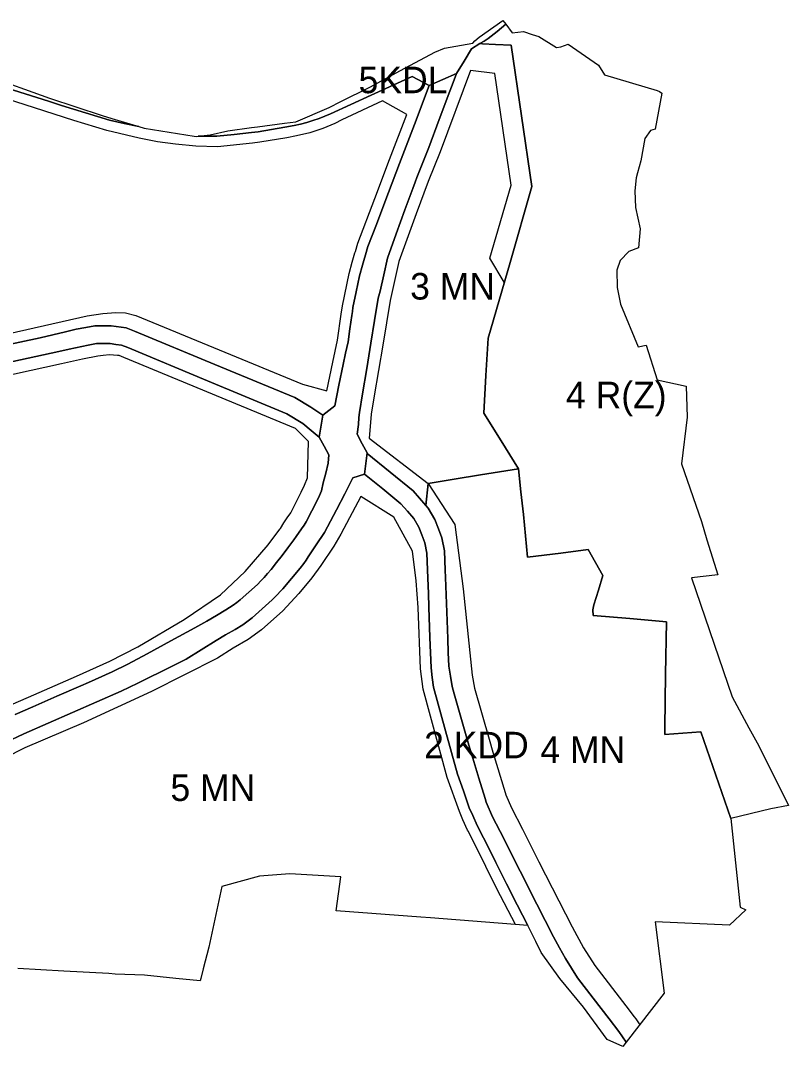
# Model space of a CAD drawing. Extents: x -295551 to -293631, y 22633 to 24461.
# Drawn here: x -294065 to -293631, y 22962 to 23541 of the extents above; entities that cross this region are included whole.
import ezdxf

# ---------------------------------------------------------------- set-up
doc = ezdxf.new("R2010")
doc.units = 0
for name, color, linetype in [('linie_rozgraniczajace', 7, 'Continuous'), ('linie_zabudowy_nieprzekraczalne', 7, 'Continuous'), ('oznaczenia_przeznaczen', 7, 'Continuous')]:
    doc.layers.add(name, color=color, linetype=linetype)

msp = doc.modelspace()

# ---------------------------------------------------------------- linework, layer by layer
at = {"layer": 'linie_rozgraniczajace'}
for points in [[(-293964.167, 23475.628), (-293957.33, 23476.38), (-293947.47, 23478.76), (-293934.05, 23480.5), (-293930.72, 23480.93), (-293915.47, 23482.97), (-293908.99, 23483.73), (-293890.08, 23491.92), (-293883.58, 23495.15), (-293867.11, 23503.35), (-293849.86, 23512.82), (-293830.42, 23523.02), (-293825.1, 23525.31), (-293809.05, 23528.15), (-293807.87, 23529.46), (-293805.42, 23531.6), (-293797.24, 23537.38), (-293792.01, 23540.98), (-293790.43, 23538.838), (-293795.371, 23534.866), (-293800.311, 23530.894), (-293802.683, 23529.408), (-293805.058, 23527.919), (-293809.809, 23524.941), (-293814.01, 23518.017), (-293818.212, 23511.093), (-293825.939, 23507.684), (-293833.667, 23504.275), (-293843.344, 23509.288), (-293866.407, 23498.811), (-293889.47, 23488.334), (-293892.68, 23486.996), (-293895.89, 23485.657), (-293899.332, 23484.511), (-293902.774, 23483.364), (-293906.346, 23482.529), (-293909.918, 23481.695), (-293915.119, 23480.653), (-293922.651, 23479.411), (-293930.183, 23478.169), (-293934.105, 23477.664), (-293943.86, 23476.644), (-293953.614, 23475.624), (-293958.89, 23475.626)], [(-293805.058, 23527.919), (-293802.683, 23529.408), (-293800.311, 23530.894), (-293795.371, 23534.866), (-293790.43, 23538.838), (-293786.87, 23534.01), (-293780.32, 23534.72), (-293775.58, 23533.17), (-293771.7, 23531.9), (-293761.82, 23525.66), (-293759.37, 23526.09), (-293755.26, 23527.56), (-293738.14, 23515.75), (-293734.64, 23510.25), (-293704.88, 23501.49), (-293703.59, 23500.81), (-293702.22, 23500), (-293706.11, 23479.61), (-293708.6, 23478.94), (-293711.95, 23474.38), (-293714.08, 23461.66), (-293716.09, 23454.95), (-293716.77, 23452.14), (-293717.48, 23444.85), (-293717.2, 23435.44), (-293714.56, 23423.34), (-293715.47, 23412.5), (-293720.92, 23410.51), (-293725.77, 23405.35), (-293727.71, 23399.89), (-293727.56, 23390.17), (-293725.63, 23380.77), (-293715.73, 23356.65), (-293711.19, 23357.65), (-293704.98, 23338.1), (-293688.52, 23334.54), (-293687.99, 23316.93), (-293691.21, 23290.55), (-293679.86, 23258.01), (-293676.87, 23247.72), (-293670.56, 23227.96), (-293685.48, 23226.2), (-293662.58, 23159.04), (-293653.07, 23141.45), (-293647.57, 23131.26), (-293630.74, 23097.6), (-293640.78, 23095.7), (-293663.22, 23090.34), (-293671.727, 23114.831), (-293680.234, 23139.321), (-293690.382, 23138.526), (-293700.53, 23137.73), (-293700.59, 23139.73), (-293700.65, 23141.73), (-293700.115, 23171.584), (-293699.581, 23201.438), (-293720.301, 23203.149), (-293741.022, 23204.86), (-293741.29, 23208.12), (-293740.6, 23210.92), (-293738.137, 23219.218), (-293735.674, 23227.516), (-293739.815, 23234.859), (-293743.957, 23242.201), (-293759.393, 23240.121), (-293778.11, 23237.86), (-293779.27, 23249.885), (-293780.43, 23261.91), (-293781.825, 23274.825), (-293783.22, 23287.74), (-293793.026, 23303.498), (-293802.831, 23319.256), (-293801.636, 23340.408), (-293800.44, 23361.56), (-293788.033, 23404.353), (-293775.627, 23447.146), (-293781.519, 23487.114), (-293787.411, 23527.082), (-293796.209, 23527.516), (-293803.567, 23527.879)], [(-293874.295, 23307.377), (-293873.681, 23312.842), (-293873.486, 23316.77), (-293873.101, 23319.613), (-293871.36, 23330.15), (-293868.99, 23344.48), (-293866.62, 23358.81), (-293864.525, 23371.5), (-293862.43, 23384.19), (-293861.42, 23388.08), (-293859.34, 23397.43), (-293857.26, 23406.78), (-293852.37, 23420.455), (-293847.48, 23434.13), (-293845.22, 23440.161), (-293842.961, 23446.192), (-293841.622, 23449.766), (-293840.68, 23452.28), (-293839.24, 23456.02), (-293833.8, 23469.24), (-293827.95, 23485.115), (-293822.1, 23500.99), (-293820.156, 23506.041), (-293818.212, 23511.093), (-293814.01, 23518.017), (-293809.809, 23524.941), (-293805.058, 23527.919), (-293803.567, 23527.879), (-293796.209, 23527.516), (-293787.411, 23527.082), (-293781.519, 23487.114), (-293775.627, 23447.146), (-293788.033, 23404.353), (-293800.44, 23361.56), (-293801.636, 23340.408), (-293802.831, 23319.256), (-293793.026, 23303.498), (-293783.22, 23287.74), (-293794, 23286.045), (-293804.78, 23284.35), (-293819.53, 23281.915), (-293834.28, 23279.48), (-293835.493, 23267.098), (-293842.79, 23275.366), (-293855.705, 23285.928), (-293868.621, 23296.49), (-293868.759, 23296.757), (-293871.458, 23301.934)], [(-294182.34, 23525.63), (-294152.87, 23524.09), (-294130.97, 23521.97), (-294126.79, 23521.57), (-294107.65, 23517.99), (-294083.96, 23509.85), (-294048.2, 23497.14), (-294018.48, 23487.36), (-294012.99, 23485.57), (-293997.701, 23481.109), (-294005.943, 23482.872), (-294014.185, 23484.635), (-294027.81, 23488.827), (-294041.436, 23493.02), (-294048.754, 23495.375), (-294068.504, 23501.732), (-294088.253, 23508.089), (-294096.884, 23510.136), (-294106.88, 23511.986), (-294144.625, 23518.811)], [(-293870.169, 23284.775), (-293869.459, 23290.755), (-293868.759, 23296.757), (-293868.621, 23296.49), (-293855.705, 23285.928), (-293842.79, 23275.366), (-293835.493, 23267.098), (-293834.162, 23265.589), (-293832.287, 23262.396), (-293830.413, 23259.203), (-293828.492, 23253.958), (-293826.572, 23248.713), (-293825.062, 23241.422), (-293824.832, 23235.946), (-293824.602, 23230.471), (-293824.435, 23226.489), (-293823.905, 23211.759), (-293823.376, 23197.029), (-293823.188, 23191.822), (-293822.911, 23184.093), (-293822.633, 23176.363), (-293821.707, 23170.579), (-293820.782, 23164.796), (-293819.6, 23160.69), (-293815.415, 23146.22), (-293811.23, 23131.75), (-293809.09, 23124.42), (-293805.595, 23112.97), (-293802.1, 23101.52), (-293801.477, 23099.482), (-293797.844, 23091.235), (-293791.604, 23078.92), (-293786.933, 23069.701), (-293782.262, 23060.483), (-293772.884, 23041.976), (-293763.506, 23023.469), (-293760.09, 23017.312), (-293756.674, 23011.156), (-293749.858, 23000.375), (-293740.984, 22988.793), (-293732.111, 22977.211), (-293726.578, 22970.001), (-293724.458, 22966.988), (-293722.338, 22963.974), (-293724.23, 22961.52), (-293733.17, 22965.49), (-293746.54, 22983.64), (-293759.96, 23000), (-293770.34, 23014.54), (-293773.46, 23020.81), (-293777.93, 23029.8), (-293784.005, 23041.545), (-293790.08, 23053.29), (-293793.05, 23059.365), (-293796.02, 23065.44), (-293799.855, 23073.079), (-293803.022, 23079.33), (-293806.547, 23086.287), (-293809.101, 23091.982), (-293811.039, 23096.381), (-293814.374, 23105.835), (-293817.71, 23115.29), (-293824.47, 23139.86), (-293831.23, 23164.43), (-293831.917, 23169.91), (-293832.604, 23175.39), (-293833.221, 23192.534), (-293833.837, 23209.678), (-293834.112, 23217.324), (-293834.427, 23226.099), (-293835.019, 23240.19), (-293836.215, 23245.966), (-293837.854, 23250.442), (-293839.493, 23254.918), (-293842.297, 23259.695), (-293845.969, 23263.856), (-293849.641, 23268.016), (-293859.905, 23276.396)], [(-293835.493, 23267.098), (-293834.28, 23279.48), (-293819.53, 23281.915), (-293804.78, 23284.35), (-293794, 23286.045), (-293783.22, 23287.74), (-293781.825, 23274.825), (-293780.43, 23261.91), (-293779.27, 23249.885), (-293778.11, 23237.86), (-293759.393, 23240.121), (-293743.957, 23242.201), (-293739.815, 23234.859), (-293735.674, 23227.516), (-293738.137, 23219.218), (-293740.6, 23210.92), (-293741.29, 23208.12), (-293741.022, 23204.86), (-293720.301, 23203.149), (-293699.581, 23201.438), (-293700.115, 23171.584), (-293700.65, 23141.73), (-293700.59, 23139.73), (-293700.53, 23137.73), (-293690.382, 23138.526), (-293680.234, 23139.321), (-293671.727, 23114.831), (-293663.22, 23090.34), (-293658.12, 23040.27), (-293654.81, 23038.76), (-293664.07, 23029.95), (-293706.09, 23031.87), (-293700.97, 22991.69), (-293722.338, 22963.974), (-293724.458, 22966.988), (-293726.578, 22970.001), (-293732.111, 22977.211), (-293740.984, 22988.793), (-293749.858, 23000.375), (-293756.674, 23011.156), (-293760.09, 23017.312), (-293763.506, 23023.469), (-293772.884, 23041.976), (-293782.262, 23060.483), (-293786.933, 23069.701), (-293791.604, 23078.92), (-293797.844, 23091.235), (-293801.477, 23099.482), (-293802.1, 23101.52), (-293805.595, 23112.97), (-293809.09, 23124.42), (-293811.23, 23131.75), (-293815.415, 23146.22), (-293819.6, 23160.69), (-293820.782, 23164.796), (-293821.707, 23170.579), (-293822.633, 23176.363), (-293822.911, 23184.093), (-293823.188, 23191.822), (-293823.376, 23197.029), (-293823.905, 23211.759), (-293824.435, 23226.489), (-293824.602, 23230.471), (-293824.832, 23235.946), (-293825.062, 23241.422), (-293826.572, 23248.713), (-293828.492, 23253.958), (-293830.413, 23259.203), (-293832.287, 23262.396), (-293834.162, 23265.589)]]:
    msp.add_lwpolyline(points, close=True, dxfattribs=at)
for points in [[(-294068.504, 23501.732), (-294048.754, 23495.375), (-294041.436, 23493.02), (-294027.81, 23488.827), (-294014.185, 23484.635), (-294005.943, 23482.872), (-293997.701, 23481.109), (-293994.62, 23480.21), (-293966.34, 23475.73), (-293965.06, 23475.53), (-293964.167, 23475.628), (-293958.89, 23475.626), (-293953.614, 23475.624), (-293943.86, 23476.644), (-293934.105, 23477.664), (-293930.183, 23478.169), (-293922.651, 23479.411), (-293915.119, 23480.653), (-293909.918, 23481.695), (-293906.346, 23482.529), (-293902.774, 23483.364), (-293899.332, 23484.511), (-293895.89, 23485.657), (-293892.68, 23486.996), (-293889.47, 23488.334), (-293866.407, 23498.811), (-293843.344, 23509.288), (-293833.667, 23504.275), (-293842.064, 23482.274), (-293850.461, 23460.273), (-293854.593, 23449.297), (-293858.724, 23438.321), (-293863.492, 23425.846), (-293868.26, 23413.37), (-293869.605, 23408.657), (-293870.617, 23405.358), (-293871.348, 23402.844), (-293873.129, 23396.718), (-293874.935, 23387.8), (-293876.741, 23378.882), (-293877.066, 23376.611), (-293877.392, 23374.34), (-293878.461, 23366.879), (-293879.53, 23359.418), (-293880.925, 23353.089), (-293882.32, 23346.76), (-293884.682, 23335.082), (-293887.044, 23323.405), (-293893.689, 23318.03), (-293900.457, 23322.525), (-293909.531, 23328.031), (-293954.841, 23346.752), (-294000.15, 23365.473), (-294004.844, 23367.335), (-294013.218, 23368.517), (-294022.454, 23368.545), (-294027.605, 23367.582), (-294033.018, 23366.57), (-294039.119, 23365.187), (-294053.48, 23361.83), (-294079.145, 23356.259)], [(-293962.695, 23199.799), (-293959.282, 23201.657), (-293953.866, 23204.857), (-293948.45, 23208.057), (-293944.438, 23210.832), (-293942.405, 23212.316), (-293940.371, 23213.8), (-293935.524, 23218.158), (-293930.678, 23222.516), (-293928.816, 23224.436), (-293926.955, 23226.356), (-293924.947, 23228.626), (-293922.938, 23230.896), (-293919.844, 23234.823), (-293916.75, 23238.75), (-293913.445, 23243.17), (-293910.14, 23247.59), (-293908.746, 23249.625), (-293905.825, 23253.843), (-293904.299, 23256.026), (-293903.252, 23257.843), (-293900.046, 23264.02), (-293896.841, 23270.198), (-293895.707, 23272.794), (-293894.574, 23275.391), (-293893.48, 23279.84), (-293892.119, 23285.361), (-293890.759, 23290.882), (-293890.393, 23295.654), (-293893.062, 23300.649), (-293895.732, 23305.644), (-293893.689, 23318.03), (-293887.044, 23323.405), (-293884.682, 23335.082), (-293882.32, 23346.76), (-293880.925, 23353.089), (-293879.53, 23359.418), (-293878.461, 23366.879), (-293877.392, 23374.34), (-293877.066, 23376.611), (-293876.741, 23378.882), (-293874.935, 23387.8), (-293873.129, 23396.718), (-293871.348, 23402.844), (-293870.617, 23405.358), (-293869.605, 23408.657), (-293868.26, 23413.37), (-293863.492, 23425.846), (-293858.724, 23438.321), (-293854.593, 23449.297), (-293850.461, 23460.273), (-293842.064, 23482.274), (-293833.667, 23504.275), (-293825.939, 23507.684), (-293818.212, 23511.093), (-293820.156, 23506.041), (-293822.1, 23500.99), (-293827.95, 23485.115), (-293833.8, 23469.24), (-293839.24, 23456.02), (-293840.68, 23452.28), (-293841.622, 23449.766), (-293842.961, 23446.192), (-293845.22, 23440.161), (-293847.48, 23434.13), (-293852.37, 23420.455), (-293857.26, 23406.78), (-293859.34, 23397.43), (-293861.42, 23388.08), (-293862.43, 23384.19), (-293864.525, 23371.5), (-293866.62, 23358.81), (-293868.99, 23344.48), (-293871.36, 23330.15), (-293873.101, 23319.613), (-293873.486, 23316.77), (-293873.681, 23312.842), (-293874.295, 23307.377), (-293871.458, 23301.934), (-293868.759, 23296.757), (-293869.459, 23290.755), (-293870.169, 23284.775), (-293876.73, 23282.75), (-293881.34, 23273.7), (-293885.95, 23264.65), (-293889.423, 23258.198), (-293892.896, 23251.747), (-293897.444, 23244.887), (-293901.993, 23238.027), (-293903.252, 23236.128), (-293904.511, 23234.229), (-293906.627, 23231.697), (-293911.527, 23225.836), (-293916.427, 23219.976), (-293917.935, 23218.42), (-293919.443, 23216.865), (-293922.349, 23213.867), (-293928.007, 23208.78), (-293933.665, 23203.692), (-293938.93, 23199.58)], [(-294079.145, 23356.259), (-294053.48, 23361.83), (-294039.119, 23365.187), (-294033.018, 23366.57), (-294027.605, 23367.582), (-294022.454, 23368.545), (-294013.218, 23368.517), (-294004.844, 23367.335), (-294000.15, 23365.473), (-293954.841, 23346.752), (-293909.531, 23328.031), (-293900.457, 23322.525), (-293893.689, 23318.03), (-293895.732, 23305.644), (-293900.425, 23309.475), (-293905.117, 23313.305), (-293914.044, 23318.78), (-293958.977, 23337.552), (-294003.91, 23356.324), (-294007.388, 23357.595), (-294010.661, 23358.057), (-294013.935, 23358.519), (-294017.739, 23358.531), (-294021.543, 23358.542), (-294026.268, 23357.659), (-294036.973, 23355.419), (-294042.952, 23354.064), (-294073.191, 23347.416)], [(-294073.191, 23347.416), (-294042.952, 23354.064), (-294036.973, 23355.419), (-294026.268, 23357.659), (-294021.543, 23358.542), (-294017.739, 23358.531), (-294013.935, 23358.519), (-294010.661, 23358.057), (-294007.388, 23357.595), (-294003.91, 23356.324), (-293958.977, 23337.552), (-293914.044, 23318.78), (-293905.117, 23313.305), (-293900.425, 23309.475), (-293895.732, 23305.644), (-293893.062, 23300.649), (-293890.393, 23295.654), (-293890.759, 23290.882), (-293892.119, 23285.361), (-293893.48, 23279.84), (-293894.574, 23275.391), (-293895.707, 23272.794), (-293896.841, 23270.198), (-293900.046, 23264.02), (-293903.252, 23257.843), (-293904.299, 23256.026), (-293905.825, 23253.843), (-293908.746, 23249.625), (-293910.14, 23247.59), (-293913.445, 23243.17), (-293916.75, 23238.75), (-293919.844, 23234.823), (-293922.938, 23230.896), (-293924.947, 23228.626), (-293926.955, 23226.356), (-293928.816, 23224.436), (-293930.678, 23222.516), (-293935.524, 23218.158), (-293940.371, 23213.8), (-293942.405, 23212.316), (-293944.438, 23210.832), (-293948.45, 23208.057), (-293953.866, 23204.857), (-293959.282, 23201.657), (-293962.695, 23199.799), (-293966.107, 23197.941), (-293979.579, 23190.604), (-293993.051, 23183.268), (-294003.837, 23177.395), (-294012.662, 23173.079), (-294022.266, 23168.852), (-294026.155, 23167.141), (-294030.395, 23165.275), (-294044.008, 23159.284), (-294057.621, 23153.292), (-294067.499, 23148.945)], [(-294073.025, 23133.131), (-294062.548, 23138.013), (-294035.078, 23150.103), (-294007.607, 23162.193), (-293998.329, 23166.73), (-293991.769, 23169.955), (-293985.21, 23173.18), (-293978.045, 23176.715), (-293970.88, 23180.25), (-293962.424, 23185.569), (-293953.968, 23190.887), (-293948.654, 23193.945), (-293943.339, 23197.002), (-293938.93, 23199.58), (-293933.665, 23203.692), (-293928.007, 23208.78), (-293922.349, 23213.867), (-293919.443, 23216.865), (-293917.935, 23218.42), (-293916.427, 23219.976), (-293911.527, 23225.836), (-293906.627, 23231.697), (-293904.511, 23234.229), (-293903.252, 23236.128), (-293901.993, 23238.027), (-293897.444, 23244.887), (-293892.896, 23251.747), (-293889.423, 23258.198), (-293885.95, 23264.65), (-293881.34, 23273.7), (-293876.73, 23282.75), (-293870.169, 23284.775), (-293859.905, 23276.396), (-293849.641, 23268.016), (-293845.969, 23263.856), (-293842.297, 23259.695), (-293839.493, 23254.918), (-293837.854, 23250.442), (-293836.215, 23245.966), (-293835.019, 23240.19), (-293834.427, 23226.099), (-293834.112, 23217.324), (-293833.837, 23209.678), (-293833.221, 23192.534), (-293832.604, 23175.39), (-293831.917, 23169.91), (-293831.23, 23164.43), (-293824.47, 23139.86), (-293817.71, 23115.29), (-293814.374, 23105.835), (-293811.039, 23096.381), (-293809.101, 23091.982), (-293806.547, 23086.287), (-293803.022, 23079.33), (-293799.855, 23073.079), (-293796.02, 23065.44), (-293793.05, 23059.365), (-293790.08, 23053.29), (-293784.005, 23041.545), (-293777.93, 23029.8), (-293832.98, 23034.12), (-293838.36, 23034.57), (-293886.21, 23038.22), (-293883.49, 23057.26), (-293912.35, 23058.96), (-293929.5, 23057.67), (-293950.78, 23051.9), (-293958.22, 23017.7), (-293961.4, 23005.29), (-293962.67, 23000), (-293963.03, 22998.55), (-293976.73, 23000), (-293994.39, 23001.87), (-294011.01, 23002.45), (-294014.7, 23002.66), (-294040.06, 23004.12), (-294066.09, 23005.62)], [(-293938.93, 23199.58), (-293943.339, 23197.002), (-293948.654, 23193.945), (-293953.968, 23190.887), (-293962.424, 23185.569), (-293970.88, 23180.25), (-293978.045, 23176.715), (-293985.21, 23173.18), (-293991.769, 23169.955), (-293998.329, 23166.73), (-294007.607, 23162.193), (-294035.078, 23150.103), (-294062.548, 23138.013), (-294073.025, 23133.131)], [(-294067.499, 23148.945), (-294057.621, 23153.292), (-294044.008, 23159.284), (-294030.395, 23165.275), (-294026.155, 23167.141), (-294022.266, 23168.852), (-294012.662, 23173.079), (-294003.837, 23177.395), (-293993.051, 23183.268), (-293979.579, 23190.604), (-293966.107, 23197.941), (-293962.695, 23199.799)]]:
    msp.add_lwpolyline(points, dxfattribs=at)
at = {"layer": 'linie_zabudowy_nieprzekraczalne'}
for points in [[(-293791.284, 23393.142), (-293799.364, 23406.717), (-293787.386, 23447.937), (-293787.386, 23447.937), (-293796.647, 23511.095), (-293810.315, 23512.75), (-293810.315, 23512.75), (-293827.486, 23466.779), (-293834.29, 23450.02), (-293834.29, 23450.02), (-293834.29, 23450.02), (-293834.29, 23450.02), (-293841.117, 23431.801), (-293850.738, 23404.896), (-293855.794, 23382.79), (-293855.794, 23382.79), (-293855.794, 23382.79), (-293859.935, 23357.704), (-293864.675, 23329.046), (-293866.4, 23318.606), (-293866.732, 23316.15), (-293866.732, 23316.15), (-293867.566, 23305.082), (-293867.566, 23305.082), (-293867.566, 23305.082), (-293867.566, 23305.082), (-293834.285, 23279.43), (-293834.285, 23279.43), (-293819.108, 23256.409), (-293819.108, 23256.409), (-293819.108, 23256.409), (-293819.108, 23256.409), (-293814.413, 23219.909), (-293814.413, 23219.909), (-293809.327, 23171.281), (-293809.327, 23171.281), (-293809.327, 23171.281), (-293807.993, 23163.987), (-293799.812, 23135.068), (-293797.697, 23127.822), (-293790.729, 23104.994), (-293790.312, 23103.63), (-293787.093, 23096.323), (-293780.998, 23084.294), (-293771.655, 23065.857), (-293753.001, 23029.042), (-293746.443, 23017.222), (-293740.094, 23007.181), (-293722.679, 22984.45), (-293717.877, 22978.193), (-293716.995, 22977.044), (-293714.737, 22973.833)], [(-294081.141, 23361.966), (-294026.79, 23374.14), (-294017.927, 23375.494), (-294010.713, 23376.101), (-294005.138, 23375.799), (-293999.304, 23374.393), (-293905.191, 23335.58), (-293891.448, 23331.828), (-293888.191, 23347.997), (-293885.437, 23360.491), (-293883.331, 23375.191), (-293882.656, 23379.903), (-293878.96, 23398.153), (-293877.109, 23404.52), (-293875.596, 23409.722), (-293875.32, 23410.493), (-293873.958, 23415.268), (-293864.334, 23440.449), (-293856.071, 23462.4), (-293846.314, 23487.964), (-293860.008, 23495.61), (-293883.029, 23484.806), (-293886.995, 23482.866), (-293893.785, 23480.034), (-293901.139, 23477.584), (-293908.646, 23475.83), (-293914.041, 23474.75), (-293929.311, 23472.232), (-293933.41, 23471.704), (-293953.302, 23469.624), (-293965.49, 23469.927), (-293976.897, 23471.067), (-293987.13, 23472.497), (-293997.543, 23474.539), (-294015.67, 23478.814), (-294034.397, 23484.576), (-294084.231, 23500.491)], [(-294069.975, 23154.411), (-294060.038, 23158.784), (-294032.812, 23170.766), (-294032.812, 23170.766), (-294032.812, 23170.766), (-294014.124, 23179.062), (-293998.149, 23187.324), (-293998.149, 23187.324), (-293971.99, 23202.668), (-293971.99, 23202.668), (-293971.99, 23202.668), (-293951.538, 23216.681), (-293951.538, 23216.681), (-293937.641, 23229.745), (-293937.641, 23229.745), (-293924.708, 23244.859), (-293924.708, 23244.859), (-293924.708, 23244.859), (-293918.05, 23253.763), (-293917.745, 23254.137), (-293915.712, 23257.204), (-293914.952, 23258.35), (-293913.473, 23260.58), (-293912.774, 23261.634), (-293911.909, 23262.94), (-293905.899, 23274.519), (-293904.11, 23278.618), (-293902.404, 23282.733), (-293901.782, 23303.121), (-293909.11, 23310.46), (-293909.11, 23310.46), (-294006.097, 23350.735), (-294008.853, 23351.743), (-294009.659, 23351.856), (-294014.162, 23352.068), (-294017.805, 23351.859), (-294020.889, 23351.373), (-294029.542, 23349.755), (-294041.391, 23347.069), (-294102.302, 23333.679)], [(-293784.971, 23030.353), (-293795.44, 23050.594), (-293801.594, 23063.18), (-293801.646, 23063.34), (-293805.207, 23070.367), (-293811.541, 23082.868), (-293811.964, 23083.702), (-293814.583, 23089.545), (-293816.621, 23094.17), (-293823.439, 23113.494), (-293837.13, 23163.255), (-293838.591, 23174.908), (-293839.833, 23209.462), (-293840.976, 23224.52), (-293843.169, 23241.362), (-293853.667, 23260.517), (-293872.359, 23272.233), (-293872.359, 23272.233), (-293883.643, 23250.843), (-293887.587, 23244.138), (-293894.801, 23233.259), (-293899.966, 23226.141), (-293907.373, 23217.352), (-293916.359, 23207.649), (-293928.299, 23196.912), (-293935.853, 23191.411), (-293944.446, 23186.401), (-293953.338, 23180.915), (-293990.591, 23161.958), (-294028.864, 23144.29), (-294062.048, 23130.139), (-294073.568, 23124.445)]]:
    msp.add_lwpolyline(points, dxfattribs=at)

# ---------------------------------------------------------------- texts
at = {"layer": 'oznaczenia_przeznaczen'}
for s, p in [('5KDL', (-293873.56, 23499.93)), ('3 MN', (-293844.422, 23383.383)), ('4 R(Z)', (-293756.406, 23321.97)), ('2 KDD', (-293836.529, 23124.25)), ('4 MN', (-293770.882, 23121.692)), ('5 MN', (-293979.831, 23100.169))]:
    msp.add_text(s, height=15, dxfattribs=at).set_placement(p)

doc.saveas('drawing.dxf')
